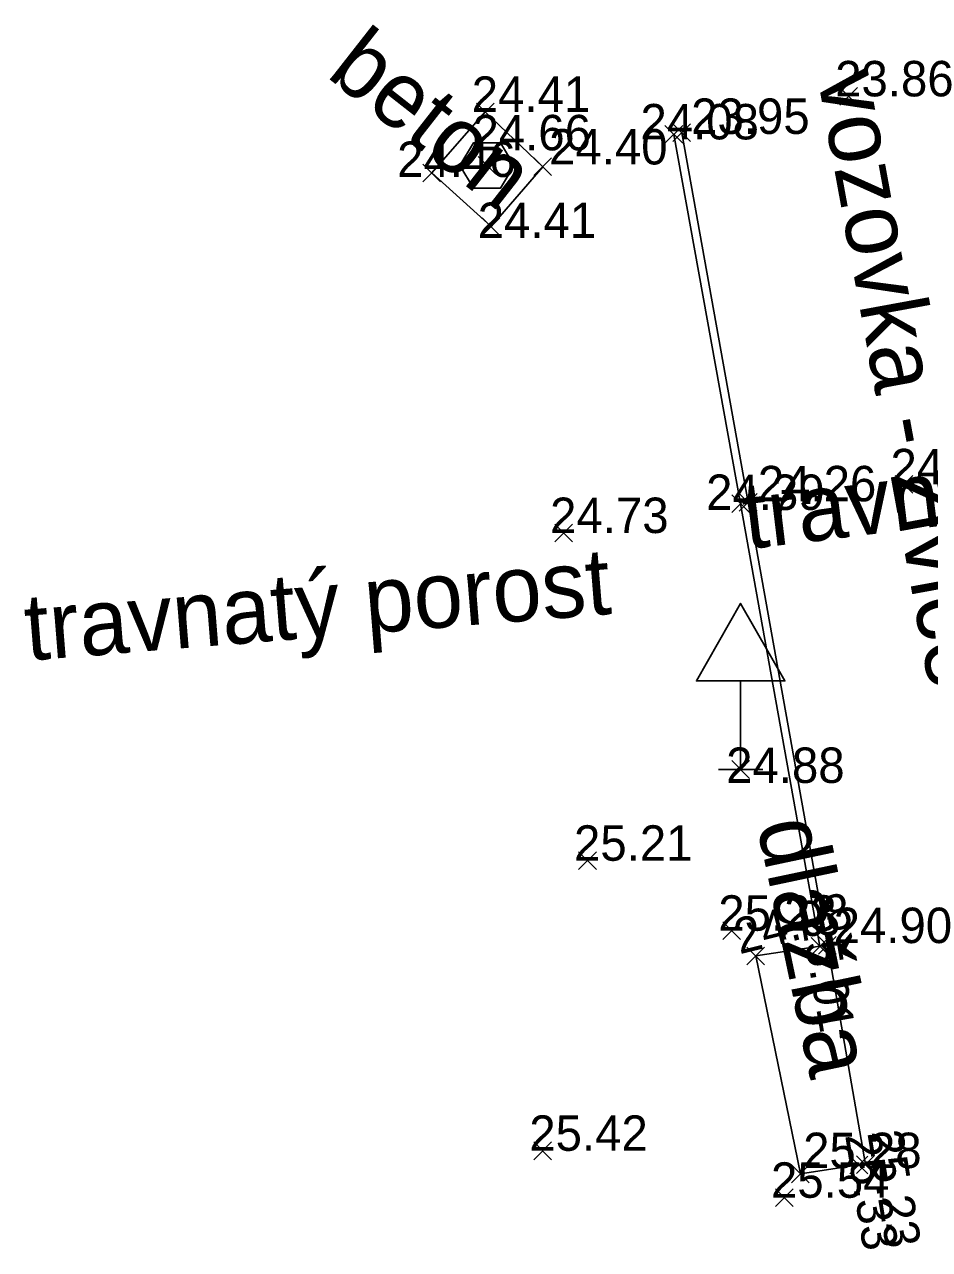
# Model space of a CAD drawing. Extents: x -772278.2 to -772217.5, y -1034079.2 to -1034029.4.
# Drawn here: x -772278.19 to -772257.74, y -1034065.87 to -1034038.21 of the extents above; entities that cross this region are included whole.
import ezdxf

# ---------------------------------------------------------------- set-up
doc = ezdxf.new("R2010")
doc.units = 0
for name, color, linetype in [('Level 16', 7, 'Continuous'), ('Level 25', 7, 'Continuous'), ('Level 26', 7, 'Continuous'), ('Level 32', 7, 'Continuous'), ('Level 36', 7, 'Continuous'), ('Level 37', 7, 'Continuous')]:
    doc.layers.add(name, color=color, linetype=linetype)

msp = doc.modelspace()

# ---------------------------------------------------------------- linework, layer by layer
at = {"layer": 'Level 16'}
for p, q in [((-772259.37, -1034040.03), (-772259.77, -1034039.63)), ((-772259.77, -1034040.03), (-772259.37, -1034039.63)), ((-772267.58, -1034040.38), (-772267.98, -1034039.98)), ((-772267.98, -1034040.38), (-772267.58, -1034039.98)), ((-772263.32, -1034040.89), (-772263.72, -1034040.49)), ((-772263.72, -1034040.89), (-772263.32, -1034040.49)), ((-772263.14, -1034040.85), (-772263.54, -1034040.45)), ((-772263.54, -1034040.85), (-772263.14, -1034040.45)), ((-772267.54, -1034041.59), (-772267.94, -1034041.19)), ((-772267.94, -1034041.59), (-772267.54, -1034041.19)), ((-772266.28, -1034041.62), (-772266.68, -1034041.22)), ((-772266.68, -1034041.62), (-772266.28, -1034041.22)), ((-772268.79, -1034041.76), (-772269.19, -1034041.36)), ((-772269.19, -1034041.76), (-772268.79, -1034041.36)), ((-772267.45, -1034042.97), (-772267.85, -1034042.57)), ((-772267.85, -1034042.97), (-772267.45, -1034042.57)), ((-772258.12, -1034048.79), (-772258.52, -1034048.39)), ((-772258.52, -1034048.79), (-772258.12, -1034048.39)), ((-772261.81, -1034049.23), (-772262.21, -1034048.83)), ((-772262.21, -1034049.23), (-772261.81, -1034048.83)), ((-772261.64, -1034049.2), (-772262.04, -1034048.8)), ((-772262.04, -1034049.2), (-772261.64, -1034048.8)), ((-772265.81, -1034049.89), (-772266.21, -1034049.49)), ((-772266.21, -1034049.89), (-772265.81, -1034049.49)), ((-772261.81, -1034055.23), (-772262.21, -1034054.83)), ((-772262.21, -1034055.23), (-772261.81, -1034054.83)), ((-772265.27, -1034057.29), (-772265.67, -1034056.89)), ((-772265.67, -1034057.29), (-772265.27, -1034056.89)), ((-772262.01, -1034058.87), (-772262.41, -1034058.47)), ((-772262.41, -1034058.87), (-772262.01, -1034058.47)), ((-772260.02, -1034059.22), (-772260.42, -1034058.82)), ((-772260.42, -1034059.22), (-772260.02, -1034058.82)), ((-772259.85, -1034059.2), (-772260.25, -1034058.8)), ((-772260.25, -1034059.2), (-772259.85, -1034058.8)), ((-772261.47, -1034059.44), (-772261.87, -1034059.04)), ((-772261.87, -1034059.44), (-772261.47, -1034059.04)), ((-772266.28, -1034063.84), (-772266.68, -1034063.44)), ((-772266.68, -1034063.84), (-772266.28, -1034063.44)), ((-772259.14, -1034064.16), (-772259.54, -1034063.76)), ((-772259.54, -1034064.16), (-772259.14, -1034063.76)), ((-772258.99, -1034064.15), (-772259.39, -1034063.75)), ((-772259.39, -1034064.15), (-772258.99, -1034063.75)), ((-772260.46, -1034064.36), (-772260.86, -1034063.96)), ((-772260.86, -1034064.36), (-772260.46, -1034063.96)), ((-772260.82, -1034064.9), (-772261.22, -1034064.5)), ((-772261.22, -1034064.9), (-772260.82, -1034064.5))]:
    msp.add_line(p, q, dxfattribs=at)
at = {"layer": 'Level 25'}
msp.add_line((-772262.51, -1034055.03), (-772261.51, -1034055.03), dxfattribs=at)
msp.add_lwpolyline([(-772262.01, -1034055.03), (-772262.01, -1034053.03), (-772261.01, -1034053.03), (-772262.01, -1034051.28), (-772263.01, -1034053.03), (-772262.01, -1034053.03)], dxfattribs=at)
at = {"layer": 'Level 26'}
msp.add_lwpolyline([(-772267.434, -1034040.88), (-772267.128, -1034041.39), (-772267.434, -1034041.9), (-772268.046, -1034041.9), (-772268.352, -1034041.39), (-772268.046, -1034040.88)], close=True, dxfattribs=at)
at = {"layer": 'Level 32'}
msp.add_line((-772260.05, -1034059), (-772259.19, -1034063.95), dxfattribs=at)
msp.add_lwpolyline([(-772266.48, -1034041.42), (-772267.78, -1034040.18), (-772268.99, -1034041.56), (-772267.65, -1034042.77)], close=True, dxfattribs=at)
for points in [[(-772263.52, -1034040.69), (-772262.01, -1034049.03), (-772260.22, -1034059.02), (-772261.67, -1034059.24), (-772260.66, -1034064.16), (-772259.34, -1034063.96), (-772259.19, -1034063.95)], [(-772263.34, -1034040.65), (-772261.84, -1034049), (-772260.05, -1034059), (-772260.22, -1034059.02)]]:
    msp.add_lwpolyline(points, dxfattribs=at)

# ---------------------------------------------------------------- texts
at = {"layer": 'Level 36'}
for s, rotation, p in [('beton', 321.945, (-772271.398, -1034039.368)), ('vozovka - živice', 280.4055, (-772260.283, -1034039.364)), ('travnatý porost', 6.8755, (-772261.868, -1034050.058)), ('travnatý porost', 4.5837, (-772278.128, -1034052.574)), ('dlažba', 281.8952, (-772261.647, -1034056.269))]:
    msp.add_text(s, height=1.5, rotation=rotation, dxfattribs=at).set_placement(p)
at = {"layer": 'Level 37'}
for s, p in [('23.86', (-772259.875, -1034039.83)), ('24.41', (-772268.085, -1034040.18)), ('23.95', (-772263.128, -1034040.678)), ('24.08', (-772264.274, -1034040.802)), ('24.66', (-772268.069, -1034041.049)), ('24.40', (-772266.338, -1034041.368)), ('24.46', (-772269.771, -1034041.65)), ('24.41', (-772267.951, -1034043.028)), ('24.19', (-772258.625, -1034048.59)), ('24.26', (-772261.622, -1034048.974)), ('24.39', (-772262.79, -1034049.169)), ('24.73', (-772266.315, -1034049.69)), ('24.88', (-772262.338, -1034055.333)), ('25.21', (-772265.775, -1034057.09)), ('25.23', (-772262.515, -1034058.67)), ('24.90', (-772259.909, -1034058.949)), ('25.42', (-772266.785, -1034063.64)), ('25.28', (-772260.598, -1034064.03)), ('25.54', (-772261.325, -1034064.7))]:
    msp.add_text(s, height=0.8, dxfattribs=at).set_placement(p)
for s, rotation, p in [('24.98', 13.8656, (-772262.036, -1034059.204)), ('25.01', 279.8326, (-772260.661, -1034058.367)), ('25.33', 279.0304, (-772259.651, -1034063.288)), ('25.23', 279.3169, (-772259.149, -1034063.237))]:
    msp.add_text(s, height=0.8, rotation=rotation, dxfattribs=at).set_placement(p)

doc.saveas('drawing.dxf')
